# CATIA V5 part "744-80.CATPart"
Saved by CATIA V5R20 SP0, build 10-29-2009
Part number: 744-80
Revision: TUTTO
Definition: NON CONOSCIUTO
Nomenclature: 744-80
Source: Unknown
Bounding box of the stored display mesh (mm): x -59 to 59, y -59.5 to 59, z -60 to 60
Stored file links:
  C:\Users\Utente\Desktop\IO LAVORO\3D X SITO CF\X SITO\744\744-80.CATPart
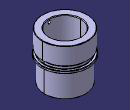
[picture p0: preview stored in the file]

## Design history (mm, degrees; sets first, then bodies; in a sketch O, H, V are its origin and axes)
Body1 "744-80 sol1" (main body)
  Solid1: solid without history
Body2 "IDV1M8_Ingrassatore-1"
  Solid2: solid without history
